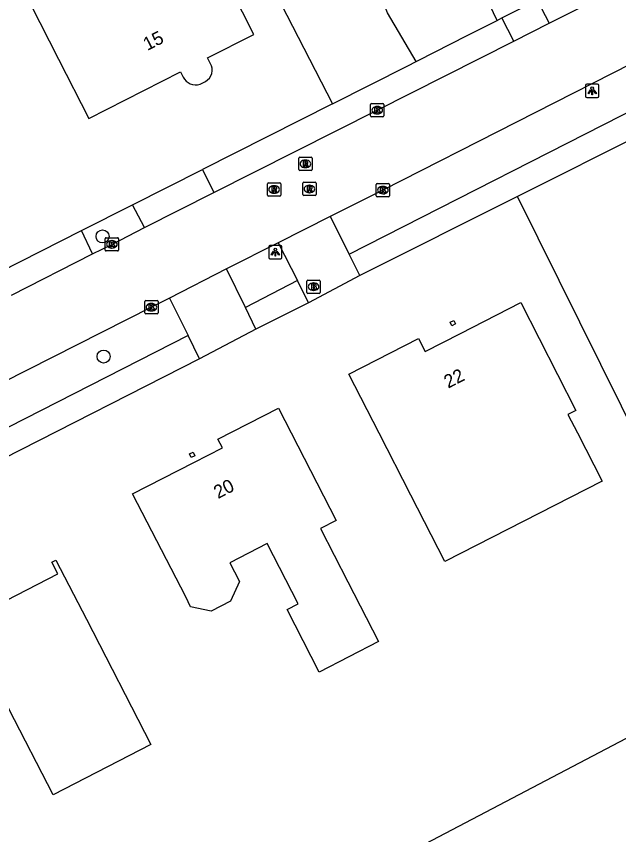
# Model space of a CAD drawing. Extents: x 162722 to 165099, y 384721 to 386283.
# Drawn here: x 163820.7 to 163865.9, y 384868.6 to 384930.1 of the extents above; entities that cross this region are included whole.
import ezdxf

# ---------------------------------------------------------------- set-up
doc = ezdxf.new("R2010")
doc.units = 0
for name, color, linetype in [('IMGEO_Boom', 7, 'Continuous'), ('IMGEO_Brandkraan', 7, 'Continuous'), ('IMGEO_Erf', 7, 'Continuous'), ('IMGEO_Groenvoorziening', 7, 'Continuous'), ('IMGEO_Kolk', 7, 'Continuous'), ('IMGEO_Lichtpunt', 7, 'Continuous'), ('IMGEO_Loofbos', 7, 'Continuous'), ('IMGEO_Pand', 7, 'Continuous'), ('IMGEO_Pand_nummerreeks', 7, 'Continuous'), ('IMGEO_Parkeervlak_open', 7, 'Continuous'), ('IMGEO_Rijbaan_lokaal_open', 7, 'Continuous'), ('IMGEO_Rioolput', 7, 'Continuous'), ('IMGEO_Voetpad_open', 7, 'Continuous')]:
    doc.layers.add(name, color=color, linetype=linetype)

msp = doc.modelspace()

# ---------------------------------------------------------------- linework, layer by layer
at = {"layer": 'IMGEO_Boom'}
for centre in [(163827.162, 384913.536), (163827.24, 384904.507)]:
    msp.add_circle(centre, 0.489, dxfattribs=at)
at = {"layer": 'IMGEO_Brandkraan'}
for p, q in [((163842.594, 384910.256), (163843.446, 384910.256)), ((163842.519, 384909.33), (163842.519, 384910.182)), ((163843.007, 384910.036), (163843.032, 384910.036)), ((163843.52, 384910.182), (163843.52, 384909.33)), ((163843.446, 384909.256), (163842.594, 384909.256)), ((163843.03, 384909.476), (163843.005, 384909.476))]:
    msp.add_line(p, q, dxfattribs=at)
for points in [[(163842.594, 384910.256), (163843.446, 384910.256)], [(163842.519, 384909.33), (163842.519, 384910.182)], [(163842.867, 384909.956), (163842.867, 384909.556), (163843.08, 384909.556)], [(163843.098, 384909.956), (163842.867, 384909.956)], [(163843.046, 384909.875), (163842.992, 384909.875), (163842.992, 384909.799)], [(163842.992, 384909.799), (163843.045, 384909.799)], [(163843.054, 384909.723), (163842.992, 384909.723), (163842.992, 384909.642)], [(163842.992, 384909.642), (163843.054, 384909.642)], [(163843.52, 384910.182), (163843.52, 384909.33)], [(163843.446, 384909.256), (163842.594, 384909.256)]]:
    msp.add_lwpolyline(points, dxfattribs=at)
for centre, radius, start, end in [((163842.596, 384910.18), 0.0765, 91.55205, 178.44795), ((163842.596, 384910.18), 0.0765, 91.55205, 178.44795), ((163843.444, 384910.18), 0.0765, 1.55205, 88.44795), ((163843.444, 384910.18), 0.0765, 1.55205, 88.44795), ((163843.047, 384909.837), 0.0379, 267.82845, 90.93552), ((163843.055, 384909.682), 0.0404, 269.87594, 90.50774), ((163843.102, 384909.811), 0.145, 59.4692, 91.53667), ((163843.127, 384909.858), 0.0922, 285.51372, 58.15012), ((163843.132, 384909.666), 0.105, 301.31148, 78.98903), ((163842.596, 384909.332), 0.0765, 181.55205, 268.44795), ((163842.596, 384909.332), 0.0765, 181.55205, 268.44795), ((163843.086, 384909.807), 0.251, 268.66757, 293.53466), ((163843.444, 384909.332), 0.0765, 271.55205, 358.44795), ((163843.444, 384909.332), 0.0765, 271.55205, 358.44795)]:
    msp.add_arc(centre, radius, start, end, dxfattribs=at)
for centre, major_axis, ratio, start_param, end_param in [((163843.006, 384909.756), (-0.387, 0.002), 0.722429, 4.712389, 7.853982), ((163843.031, 384909.756), (-0.39, 0.002), 0.717154, 1.570796, 4.712389)]:
    msp.add_ellipse(centre, major_axis=major_axis, ratio=ratio, start_param=start_param, end_param=end_param, dxfattribs=at)
at = {"layer": 'IMGEO_Erf'}
msp.add_lwpolyline([(163876.056, 384880.802), (163840.837, 384862.308), (163841.154, 384861.667), (163822.396, 384853.228), (163804.848, 384844.548), (163789.755, 384835.805)], dxfattribs=at)
at = {"layer": 'IMGEO_Groenvoorziening'}
for points in [[(163792.25, 385001.396), (163802.343, 385006.509), (163805.625, 385000), (163810.019, 384991.283), (163815.938, 384979.592), (163818.047, 384980.633), (163823.424, 384970.076), (163821.324, 384968.955), (163837.132, 384937.732), (163844.43, 384923.507)], [(163850.721, 384926.692), (163848.58, 384930.349), (163846.709, 384935.032), (163844.556, 384940.861), (163842.832, 384945.951), (163840.819, 384951.291), (163838.385, 384956.066), (163834.732, 384959.963), (163833.717, 384961.939), (163831.854, 384966.281), (163829.673, 384970.329), (163827.544, 384974.063), (163828.596, 384975.798), (163825.844, 384980.889), (163823.674, 384985.023), (163822.453, 384988.419), (163821.501, 384989.907)], [(163856.826, 384929.784), (163840.9, 384963.114), (163834.379, 384974.661), (163827.686, 384987.569), (163826.306, 384989.862), (163821.501, 384989.907)]]:
    msp.add_lwpolyline(points, dxfattribs=at)
at = {"layer": 'IMGEO_Kolk'}
for p, q in [((163847.302, 384922.599), (163847.302, 384923.451)), ((163847.377, 384923.525), (163848.229, 384923.525)), ((163847.79, 384923.305), (163847.815, 384923.305)), ((163848.303, 384923.451), (163848.303, 384922.599)), ((163847.813, 384922.745), (163847.788, 384922.745)), ((163848.229, 384922.525), (163847.377, 384922.525)), ((163847.725, 384916.596), (163847.725, 384917.448)), ((163847.8, 384917.522), (163848.652, 384917.522)), ((163848.213, 384917.302), (163848.238, 384917.302)), ((163848.726, 384917.448), (163848.726, 384916.596)), ((163848.652, 384916.522), (163847.8, 384916.522)), ((163848.236, 384916.742), (163848.211, 384916.742)), ((163827.359, 384912.516), (163827.359, 384913.368)), ((163827.434, 384913.442), (163828.286, 384913.442)), ((163828.36, 384913.368), (163828.36, 384912.516)), ((163827.847, 384913.222), (163827.872, 384913.222)), ((163828.286, 384912.442), (163827.434, 384912.442)), ((163827.87, 384912.662), (163827.845, 384912.662)), ((163830.332, 384907.787), (163830.332, 384908.639)), ((163830.407, 384908.713), (163831.259, 384908.713)), ((163830.82, 384908.493), (163830.845, 384908.493)), ((163831.333, 384908.639), (163831.333, 384907.787)), ((163830.843, 384907.933), (163830.818, 384907.933)), ((163831.259, 384907.713), (163830.407, 384907.713))]:
    msp.add_line(p, q, dxfattribs=at)
for points in [[(163847.302, 384922.599), (163847.302, 384923.451)], [(163847.377, 384923.525), (163848.229, 384923.525)], [(163847.623, 384923.225), (163847.746, 384923.225), (163847.746, 384923.074), (163847.876, 384923.225), (163848.04, 384923.225), (163847.894, 384923.074), (163848.047, 384922.825), (163847.895, 384922.825), (163847.81, 384922.989), (163847.746, 384922.922), (163847.746, 384922.825), (163847.623, 384922.825), (163847.623, 384923.225)], [(163848.303, 384923.451), (163848.303, 384922.599)], [(163848.229, 384922.525), (163847.377, 384922.525)], [(163847.725, 384916.596), (163847.725, 384917.448)], [(163847.8, 384917.522), (163848.652, 384917.522)], [(163848.046, 384917.222), (163848.169, 384917.222), (163848.169, 384917.071), (163848.299, 384917.222), (163848.463, 384917.222), (163848.317, 384917.071), (163848.47, 384916.822), (163848.318, 384916.822), (163848.233, 384916.986), (163848.169, 384916.919), (163848.169, 384916.822), (163848.046, 384916.822), (163848.046, 384917.222)], [(163848.726, 384917.448), (163848.726, 384916.596)], [(163848.652, 384916.522), (163847.8, 384916.522)], [(163827.359, 384912.516), (163827.359, 384913.368)], [(163827.434, 384913.442), (163828.286, 384913.442)], [(163828.36, 384913.368), (163828.36, 384912.516)], [(163827.68, 384913.142), (163827.803, 384913.142), (163827.803, 384912.991), (163827.933, 384913.142), (163828.097, 384913.142), (163827.951, 384912.991), (163828.104, 384912.742), (163827.952, 384912.742), (163827.867, 384912.906), (163827.803, 384912.839), (163827.803, 384912.742), (163827.68, 384912.742), (163827.68, 384913.142)], [(163828.286, 384912.442), (163827.434, 384912.442)], [(163830.332, 384907.787), (163830.332, 384908.639)], [(163830.407, 384908.713), (163831.259, 384908.713)], [(163830.653, 384908.413), (163830.776, 384908.413), (163830.776, 384908.262), (163830.906, 384908.413), (163831.07, 384908.413), (163830.924, 384908.262), (163831.077, 384908.013), (163830.925, 384908.013), (163830.84, 384908.177), (163830.776, 384908.11), (163830.776, 384908.013), (163830.653, 384908.013), (163830.653, 384908.413)], [(163831.333, 384908.639), (163831.333, 384907.787)], [(163831.259, 384907.713), (163830.407, 384907.713)]]:
    msp.add_lwpolyline(points, dxfattribs=at)
for centre, start, end in [((163847.379, 384923.449), 91.55205, 178.44795), ((163847.379, 384923.449), 91.55205, 178.44795), ((163848.227, 384923.449), 1.55205, 88.44795), ((163848.227, 384923.449), 1.55205, 88.44795), ((163847.379, 384922.601), 181.55205, 268.44795), ((163847.379, 384922.601), 181.55205, 268.44795), ((163848.227, 384922.601), 271.55205, 358.44795), ((163848.227, 384922.601), 271.55205, 358.44795), ((163847.802, 384917.446), 91.55205, 178.44795), ((163847.802, 384917.446), 91.55205, 178.44795), ((163848.65, 384917.446), 1.55205, 88.44795), ((163848.65, 384917.446), 1.55205, 88.44795), ((163847.802, 384916.598), 181.55205, 268.44795), ((163847.802, 384916.598), 181.55205, 268.44795), ((163848.65, 384916.598), 271.55205, 358.44795), ((163848.65, 384916.598), 271.55205, 358.44795), ((163827.436, 384913.366), 91.55205, 178.44795), ((163827.436, 384913.366), 91.55205, 178.44795), ((163828.284, 384913.366), 1.55205, 88.44795), ((163828.284, 384913.366), 1.55205, 88.44795), ((163827.436, 384912.518), 181.55205, 268.44795), ((163827.436, 384912.518), 181.55205, 268.44795), ((163828.284, 384912.518), 271.55205, 358.44795), ((163828.284, 384912.518), 271.55205, 358.44795), ((163830.409, 384908.637), 91.55205, 178.44795), ((163830.409, 384908.637), 91.55205, 178.44795), ((163831.257, 384908.637), 1.55205, 88.44795), ((163831.257, 384908.637), 1.55205, 88.44795), ((163830.409, 384907.789), 181.55205, 268.44795), ((163830.409, 384907.789), 181.55205, 268.44795), ((163831.257, 384907.789), 271.55205, 358.44795), ((163831.257, 384907.789), 271.55205, 358.44795)]:
    msp.add_arc(centre, 0.0765, start, end, dxfattribs=at)
for centre, major_axis, ratio, start_param, end_param in [((163847.789, 384923.025), (-0.387, 0.002), 0.722429, 4.712389, 7.853982), ((163847.814, 384923.025), (-0.39, 0.002), 0.717154, 1.570796, 4.712389), ((163848.212, 384917.022), (-0.387, 0.002), 0.722429, 4.712389, 7.853982), ((163848.237, 384917.022), (-0.39, 0.002), 0.717154, 1.570796, 4.712389), ((163827.846, 384912.942), (-0.387, 0.002), 0.722429, 4.712389, 7.853982), ((163827.871, 384912.942), (-0.39, 0.002), 0.717154, 1.570796, 4.712389), ((163830.819, 384908.213), (-0.387, 0.002), 0.722429, 4.712389, 7.853982), ((163830.844, 384908.213), (-0.39, 0.002), 0.717154, 1.570796, 4.712389)]:
    msp.add_ellipse(centre, major_axis=major_axis, ratio=ratio, start_param=start_param, end_param=end_param, dxfattribs=at)
at = {"layer": 'IMGEO_Lichtpunt'}
for p, q in [((163863.46, 384924.887), (163863.46, 384924.08)), ((163863.46, 384924.887), (163863.46, 384924.08)), ((163864.362, 384924.982), (163863.554, 384924.982)), ((163864.362, 384924.982), (163863.554, 384924.982)), ((163864.456, 384924.08), (163864.456, 384924.887)), ((163864.456, 384924.08), (163864.456, 384924.887)), ((163863.554, 384923.986), (163864.362, 384923.986)), ((163863.554, 384923.986), (163864.362, 384923.986)), ((163839.645, 384912.756), (163839.645, 384911.949)), ((163839.645, 384912.756), (163839.645, 384911.949)), ((163840.547, 384912.851), (163839.739, 384912.851)), ((163840.547, 384912.851), (163839.739, 384912.851)), ((163840.641, 384911.949), (163840.641, 384912.756)), ((163840.641, 384911.949), (163840.641, 384912.756)), ((163839.739, 384911.855), (163840.547, 384911.855)), ((163839.739, 384911.855), (163840.547, 384911.855))]:
    msp.add_line(p, q, dxfattribs=at)
for points in [[(163863.834, 384924.551), (163863.873, 384924.523), (163863.685, 384924.261), (163863.647, 384924.288), (163863.834, 384924.551)], [(163863.936, 384924.503), (163863.983, 384924.503), (163863.983, 384924.181), (163863.936, 384924.181), (163863.936, 384924.503)], [(163864.046, 384924.523), (163864.084, 384924.55), (163864.271, 384924.288), (163864.232, 384924.26), (163864.046, 384924.523)], [(163840.019, 384912.42), (163840.058, 384912.392), (163839.87, 384912.13), (163839.832, 384912.157), (163840.019, 384912.42)], [(163840.121, 384912.372), (163840.168, 384912.372), (163840.168, 384912.05), (163840.121, 384912.05), (163840.121, 384912.372)], [(163840.231, 384912.392), (163840.269, 384912.419), (163840.456, 384912.157), (163840.417, 384912.129), (163840.231, 384912.392)]]:
    msp.add_lwpolyline(points, dxfattribs=at)
for centre in [(163863.959, 384924.685), (163840.144, 384912.554)]:
    msp.add_circle(centre, 0.0994, dxfattribs=at)
for centre, start, end in [((163863.554, 384924.887), 90, 180), ((163863.554, 384924.887), 90, 180), ((163864.362, 384924.887), 0, 90), ((163864.362, 384924.887), 0, 90), ((163863.554, 384924.08), 180, 270), ((163863.554, 384924.08), 180, 270), ((163864.362, 384924.08), 270, 0), ((163864.362, 384924.08), 270, 360), ((163839.739, 384912.756), 90, 180), ((163839.739, 384912.756), 90, 180), ((163840.547, 384912.756), 0, 90), ((163840.547, 384912.756), 0, 90), ((163839.739, 384911.949), 180, 270), ((163839.739, 384911.949), 180, 270), ((163840.547, 384911.949), 270, 0), ((163840.547, 384911.949), 270, 360)]:
    msp.add_arc(centre, 0.0946, start, end, dxfattribs=at)
at = {"layer": 'IMGEO_Loofbos'}
msp.add_lwpolyline([(163876.056, 384880.802), (163873.969, 384885.011), (163858.338, 384916.535)], dxfattribs=at)
at = {"layer": 'IMGEO_Pand'}
for points in [[(163835.259, 384926.552), (163835.054, 384926.953), (163838.531, 384928.718), (163833.458, 384938.708), (163829, 384936.444), (163821.046, 384932.405), (163823.854, 384926.874), (163826.118, 384922.415), (163833.011, 384925.915), (163833.216, 384925.514)], [(163834.486, 384924.982), (163834.888, 384925.186)], [(163847.941, 384898.741), (163845.664, 384903.192), (163850.904, 384905.872), (163851.407, 384904.888), (163854.053, 384906.242), (163858.587, 384908.561), (163862.737, 384900.448), (163862.135, 384900.14), (163862.842, 384898.758), (163864.695, 384895.135), (163852.878, 384889.09), (163850.33, 384894.071), (163847.941, 384898.741)], [(163853.273, 384907.084), (163853.549, 384907.225), (163853.686, 384906.958), (163853.41, 384906.817), (163853.273, 384907.084)], [(163845.585, 384887.575), (163847.904, 384883.07), (163843.441, 384880.773), (163841.021, 384885.477), (163841.854, 384885.906), (163839.52, 384890.441), (163836.72, 384888.999), (163837.071, 384888.316), (163837.447, 384887.585), (163836.771, 384886.102), (163835.33, 384885.362), (163833.768, 384885.683), (163833.408, 384886.431), (163829.422, 384894.174), (163834.016, 384896.538), (163836.166, 384897.644), (163835.836, 384898.285), (163840.381, 384900.625), (163844.725, 384892.186), (163843.529, 384891.57), (163845.585, 384887.575)], [(163834.103, 384897.045), (163833.827, 384896.903), (163833.685, 384897.178), (163833.961, 384897.32), (163834.103, 384897.045)], [(163830.79, 384875.34), (163823.453, 384871.563), (163820.13, 384878.019), (163819.111, 384879.998), (163813.991, 384877.362), (163813.485, 384878.345), (163811.197, 384882.79), (163817.928, 384886.255), (163818.382, 384885.375), (163823.797, 384888.163), (163823.343, 384889.043), (163823.654, 384889.203), (163825.942, 384884.758), (163830.79, 384875.34)]]:
    msp.add_lwpolyline(points, dxfattribs=at)
for centre, radius, start, end in [((163834.403, 384926.051), 0.992, 299.285, 30.32547), ((163834.168, 384926.005), 1.071, 207.27727, 287.26534)]:
    msp.add_arc(centre, radius, start, end, dxfattribs=at)
at = {"layer": 'IMGEO_Parkeervlak_open'}
for points in [[(163856.826, 384929.784), (163857.177, 384929.962)], [(163850.721, 384926.692), (163850.884, 384926.775), (163854.555, 384928.634), (163856.826, 384929.784)], [(163844.43, 384923.507), (163850.092, 384926.374), (163850.721, 384926.692)], [(163844.43, 384923.507), (163834.666, 384918.562)], [(163825.569, 384913.978), (163829.408, 384915.914)]]:
    msp.add_lwpolyline(points, dxfattribs=at)
at = {"layer": 'IMGEO_Rijbaan_lokaal_open'}
for points in [[(163860.722, 384929.573), (163865.823, 384932.161), (163873.077, 384935.831), (163882.365, 384940.529), (163900.427, 384949.633), (163902.168, 384950.54), (163902.719, 384950.896)], [(163894.005, 384940.23), (163884.811, 384935.58), (163875.45, 384930.841), (163868.32, 384927.232), (163848.226, 384917.022), (163844.277, 384915.026)], [(163858.06, 384928.229), (163860.722, 384929.573)], [(163835.53, 384916.828), (163847.803, 384923.025), (163858.06, 384928.229)], [(163830.317, 384914.202), (163835.53, 384916.828)], [(163844.277, 384915.026), (163840.363, 384913.049)], [(163826.397, 384912.222), (163827.86, 384912.942), (163830.317, 384914.202)], [(163840.363, 384913.049), (163836.485, 384911.089)], [(163820.324, 384909.131), (163826.397, 384912.222)], [(163836.485, 384911.089), (163832.186, 384908.893)], [(163832.186, 384908.893), (163830.833, 384908.213), (163819.657, 384902.552), (163817.34, 384901.422)]]:
    msp.add_lwpolyline(points, dxfattribs=at)
at = {"layer": 'IMGEO_Rioolput'}
for p, q in [((163841.976, 384919.493), (163842.828, 384919.493)), ((163841.901, 384918.567), (163841.901, 384919.419)), ((163842.389, 384919.273), (163842.414, 384919.273)), ((163842.902, 384919.419), (163842.902, 384918.567)), ((163842.828, 384918.493), (163841.976, 384918.493)), ((163842.412, 384918.713), (163842.387, 384918.713)), ((163839.554, 384916.641), (163839.554, 384917.493)), ((163839.629, 384917.567), (163840.481, 384917.567)), ((163840.042, 384917.347), (163840.067, 384917.347)), ((163840.555, 384917.493), (163840.555, 384916.641)), ((163842.209, 384916.68), (163842.209, 384917.532)), ((163842.284, 384917.606), (163843.136, 384917.606)), ((163842.697, 384917.386), (163842.722, 384917.386)), ((163843.21, 384917.532), (163843.21, 384916.68)), ((163840.481, 384916.567), (163839.629, 384916.567)), ((163840.065, 384916.787), (163840.04, 384916.787)), ((163843.136, 384916.606), (163842.284, 384916.606)), ((163842.72, 384916.826), (163842.695, 384916.826))]:
    msp.add_line(p, q, dxfattribs=at)
for points in [[(163841.976, 384919.493), (163842.828, 384919.493)], [(163841.901, 384918.567), (163841.901, 384919.419)], [(163842.49, 384919.191), (163842.238, 384919.193), (163842.238, 384918.793)], [(163842.238, 384918.793), (163842.362, 384918.793), (163842.362, 384918.955), (163842.373, 384918.955)], [(163842.416, 384919.112), (163842.362, 384919.112), (163842.362, 384919.031)], [(163842.362, 384919.031), (163842.414, 384919.031)], [(163842.42, 384918.926), (163842.491, 384918.793), (163842.631, 384918.793), (163842.566, 384918.919)], [(163842.902, 384919.419), (163842.902, 384918.567)], [(163842.828, 384918.493), (163841.976, 384918.493)], [(163839.554, 384916.641), (163839.554, 384917.493)], [(163839.629, 384917.567), (163840.481, 384917.567)], [(163840.143, 384917.265), (163839.891, 384917.267), (163839.891, 384916.867)], [(163839.891, 384916.867), (163840.015, 384916.867), (163840.015, 384917.029), (163840.026, 384917.029)], [(163840.069, 384917.186), (163840.015, 384917.186), (163840.015, 384917.105)], [(163840.015, 384917.105), (163840.067, 384917.105)], [(163840.555, 384917.493), (163840.555, 384916.641)], [(163842.209, 384916.68), (163842.209, 384917.532)], [(163842.284, 384917.606), (163843.136, 384917.606)], [(163842.798, 384917.304), (163842.546, 384917.306), (163842.546, 384916.906)], [(163842.546, 384916.906), (163842.67, 384916.906), (163842.67, 384917.068), (163842.681, 384917.068)], [(163842.724, 384917.225), (163842.67, 384917.225), (163842.67, 384917.144)], [(163842.67, 384917.144), (163842.722, 384917.144)], [(163842.728, 384917.039), (163842.799, 384916.906), (163842.939, 384916.906), (163842.874, 384917.032)], [(163843.21, 384917.532), (163843.21, 384916.68)], [(163840.481, 384916.567), (163839.629, 384916.567)], [(163840.073, 384917), (163840.144, 384916.867), (163840.284, 384916.867), (163840.219, 384916.993)], [(163843.136, 384916.606), (163842.284, 384916.606)]]:
    msp.add_lwpolyline(points, dxfattribs=at)
for centre, radius, start, end in [((163841.978, 384919.417), 0.0765, 91.55205, 178.44795), ((163841.978, 384919.417), 0.0765, 91.55205, 178.44795), ((163842.826, 384919.417), 0.0765, 1.55205, 88.44795), ((163842.826, 384919.417), 0.0765, 1.55205, 88.44795), ((163842.372, 384918.902), 0.0533, 26.02933, 88.69889), ((163842.398, 384919.22), 0.19, 274.7715, 282.96867), ((163842.422, 384919.016), 0.0964, 77.00612, 93.18647), ((163842.436, 384919.073), 0.0378, 276.66336, 79.67722), ((163842.489, 384919.081), 0.109, 350.36119, 89.41601), ((163842.487, 384919.081), 0.112, 277.58423, 350.98172), ((163842.471, 384918.866), 0.108, 29.51342, 73.79051), ((163841.978, 384918.569), 0.0765, 181.55205, 268.44795), ((163841.978, 384918.569), 0.0765, 181.55205, 268.44795), ((163842.826, 384918.569), 0.0765, 271.55205, 358.44795), ((163842.826, 384918.569), 0.0765, 271.55205, 358.44795), ((163839.631, 384917.491), 0.0765, 91.55205, 178.44795), ((163839.631, 384917.491), 0.0765, 91.55205, 178.44795), ((163840.025, 384916.976), 0.0533, 26.02933, 88.69889), ((163840.051, 384917.294), 0.19, 274.7715, 282.96867), ((163840.075, 384917.09), 0.0964, 77.00612, 93.18647), ((163840.089, 384917.147), 0.0378, 276.66336, 79.67722), ((163840.142, 384917.155), 0.109, 350.36119, 89.41601), ((163840.14, 384917.155), 0.112, 277.58423, 350.98172), ((163840.124, 384916.94), 0.108, 29.51342, 73.79051), ((163840.479, 384917.491), 0.0765, 1.55205, 88.44795), ((163840.479, 384917.491), 0.0765, 1.55205, 88.44795), ((163842.286, 384917.53), 0.0765, 91.55205, 178.44795), ((163842.286, 384917.53), 0.0765, 91.55205, 178.44795), ((163842.68, 384917.015), 0.0533, 26.02933, 88.69889), ((163842.706, 384917.333), 0.19, 274.7715, 282.96867), ((163842.73, 384917.129), 0.0964, 77.00612, 93.18647), ((163842.744, 384917.186), 0.0378, 276.66336, 79.67722), ((163842.797, 384917.194), 0.109, 350.36119, 89.41601), ((163842.795, 384917.194), 0.112, 277.58423, 350.98172), ((163842.779, 384916.979), 0.108, 29.51342, 73.79051), ((163843.134, 384917.53), 0.0765, 1.55205, 88.44795), ((163843.134, 384917.53), 0.0765, 1.55205, 88.44795), ((163839.631, 384916.643), 0.0765, 181.55205, 268.44795), ((163839.631, 384916.643), 0.0765, 181.55205, 268.44795), ((163840.479, 384916.643), 0.0765, 271.55205, 358.44795), ((163840.479, 384916.643), 0.0765, 271.55205, 358.44795), ((163842.286, 384916.682), 0.0765, 181.55205, 268.44795), ((163842.286, 384916.682), 0.0765, 181.55205, 268.44795), ((163843.134, 384916.682), 0.0765, 271.55205, 358.44795), ((163843.134, 384916.682), 0.0765, 271.55205, 358.44795)]:
    msp.add_arc(centre, radius, start, end, dxfattribs=at)
for centre, major_axis, ratio, start_param, end_param in [((163842.388, 384918.993), (-0.387, 0.002), 0.722429, 4.712389, 7.853982), ((163842.413, 384918.993), (-0.39, 0.002), 0.717154, 1.570796, 4.712389), ((163840.041, 384917.067), (-0.387, 0.002), 0.722429, 4.712389, 7.853982), ((163840.066, 384917.067), (-0.39, 0.002), 0.717154, 1.570796, 4.712389), ((163842.696, 384917.106), (-0.387, 0.002), 0.722429, 4.712389, 7.853982), ((163842.721, 384917.106), (-0.39, 0.002), 0.717154, 1.570796, 4.712389)]:
    msp.add_ellipse(centre, major_axis=major_axis, ratio=ratio, start_param=start_param, end_param=end_param, dxfattribs=at)
at = {"layer": 'IMGEO_Voetpad_open'}
for points in [[(163845.685, 384912.215), (163868.912, 384924.044), (163876.924, 384928.111), (163895.383, 384937.48)], [(163857.177, 384929.962), (163859.812, 384931.297)], [(163859.812, 384931.297), (163860.722, 384929.573)], [(163858.06, 384928.229), (163857.177, 384929.962)], [(163867.928, 384921.346), (163858.338, 384916.535)], [(163829.408, 384915.914), (163834.666, 384918.562)], [(163834.666, 384918.562), (163835.53, 384916.828)], [(163858.338, 384916.535), (163846.504, 384910.599)], [(163830.317, 384914.202), (163829.408, 384915.914)], [(163844.277, 384915.026), (163845.685, 384912.215)], [(163819.455, 384910.881), (163825.569, 384913.978)], [(163826.397, 384912.222), (163825.569, 384913.978)], [(163840.363, 384913.049), (163841.808, 384910.217)], [(163846.504, 384910.599), (163845.685, 384912.215)], [(163837.907, 384908.192), (163836.485, 384911.089)], [(163846.504, 384910.599), (163842.648, 384908.55)], [(163841.808, 384910.217), (163837.907, 384908.192)], [(163842.648, 384908.55), (163841.808, 384910.217)], [(163832.186, 384908.893), (163833.587, 384906.081)], [(163842.648, 384908.55), (163838.68, 384906.565)], [(163838.68, 384906.565), (163837.907, 384908.192)], [(163838.68, 384906.565), (163834.445, 384904.343)], [(163833.587, 384906.081), (163818.836, 384898.572)], [(163834.445, 384904.343), (163833.587, 384906.081)], [(163834.445, 384904.343), (163819.7, 384896.812)]]:
    msp.add_lwpolyline(points, dxfattribs=at)

# ---------------------------------------------------------------- texts
at = {"layer": 'IMGEO_Pand_nummerreeks'}
for s, rotation, p in [('15', 26.92028, (163830.529, 384927.48)), ('22', 27.09246, (163853.133, 384902.087)), ('20', 27.22724, (163835.836, 384893.785))]:
    msp.add_text(s, height=1, rotation=rotation, dxfattribs=at).set_placement(p)

doc.saveas('drawing.dxf')
